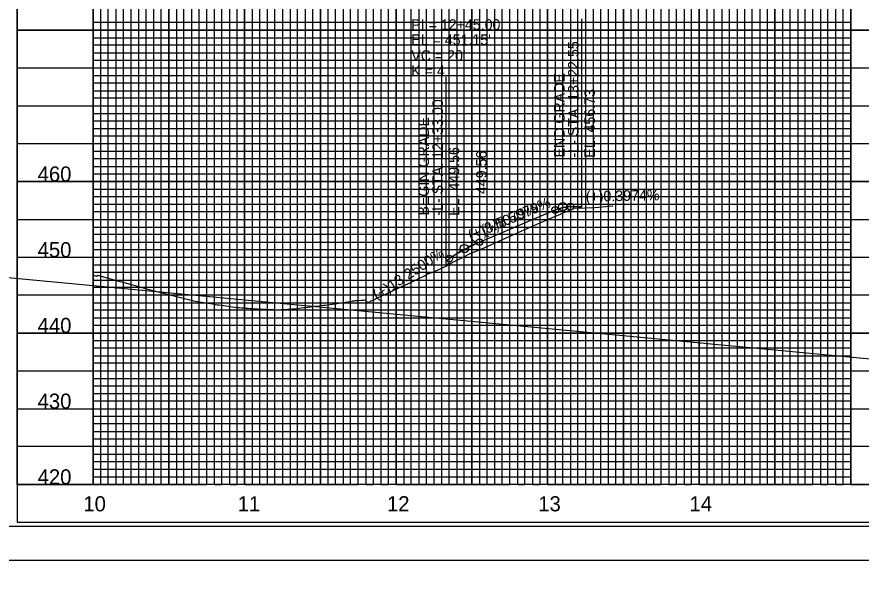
# Model space of a CAD drawing. Extents: x 571503 to 593215, y -77195 to -51828.
# Drawn here: x 585926 to 586483, y -53731 to -53362 of the extents above; entities that cross this region are included whole.
import ezdxf

# ---------------------------------------------------------------- set-up
doc = ezdxf.new("R2010")
doc.units = 0
for name, color, linetype in [('Default', 7, 'Continuous'), ('Exist Vertical Profile Ground Line', 7, 'Continuous'), ('Exist Vertical Profile Horizontal Axis Label Major', 7, 'Continuous'), ('Exist Vertical Profile Vertical Axis Label', 7, 'Continuous'), ('Prop PFL Text', 7, 'Continuous'), ('Prop Vertical Profile Curve Label', 7, 'Continuous'), ('Prop Vertical Profile Grade', 7, 'Continuous'), ('Prop Vertical Profile Grade Label', 7, 'Continuous'), ('Prop VPI Label', 7, 'Continuous'), ('Sheet Clip Boundary CELL', 7, 'Continuous'), ('Sheet DOT Grid CELL', 7, 'Continuous'), ('Sheet Plot Border Inside CELL', 7, 'Continuous'), ('Sheet Plot Border Outside CELL', 7, 'Continuous'), ('Sheet Profile CELL', 7, 'Continuous'), ('Sheet Profile Grid Major CELL', 7, 'Continuous'), ('Sheet Profile Grid Middle CELL', 7, 'Continuous'), ('Sheet Profile Grid Minor CELL', 7, 'Continuous')]:
    doc.layers.add(name, color=color, linetype=linetype)

msp = doc.modelspace()

# ---------------------------------------------------------------- linework, layer by layer
at = {"layer": 'Default'}
msp.add_line((585925.93, -53671.12), (585975.93, -53671.12), dxfattribs=at)
at = {"layer": 'Exist Vertical Profile Ground Line'}
for points in [[(586199.68, -53531.22), (586206.18, -53528.39), (586209.14, -53526.7), (586212.57, -53524.71), (586220.67, -53520.84), (586224.86, -53518.65), (586226.58, -53517.88), (586234.51, -53514.55), (586252.46, -53506.44), (586266.41, -53500.35), (586279.93, -53494.38), (586283.99, -53492.92), (586286.24, -53491.75), (586287.94, -53490.99), (586289.4, -53490.48), (586290.66, -53490), (586291.54, -53489.74)], [(586291.54, -53489.74), (586293.26, -53488.87), (586293.34, -53488.82), (586293.54, -53488.77), (586307.39, -53488.18), (586318.8, -53487.13), (586318.98, -53487.12)], [(585975.93, -53532.69), (585975.94, -53532.69), (585977.31, -53533.36), (585978.23, -53533.49), (585979.04, -53532.99), (585993.54, -53537.05), (585994.82, -53537.32), (586010.54, -53541.64), (586012.14, -53542.08), (586028.41, -53546.45), (586043.24, -53550.02), (586050.43, -53551.22), (586051.89, -53551.47), (586053.35, -53551.71), (586054.81, -53551.95), (586056.28, -53552.2), (586056.82, -53552.29), (586057.74, -53552.41), (586059.2, -53552.6), (586060.67, -53552.8), (586062.13, -53553), (586063.59, -53553.19), (586065.06, -53553.39), (586066.52, -53553.59), (586067.98, -53553.79), (586069.45, -53553.98), (586070.91, -53554.18), (586072.09, -53554.34), (586072.37, -53554.36), (586073.84, -53554.47), (586075.3, -53554.58), (586076.76, -53554.68), (586078.23, -53554.79), (586079.69, -53554.89), (586081.15, -53555), (586082.62, -53555.1), (586084.08, -53555.21), (586084.53, -53555.24), (586085.54, -53555.28), (586087.01, -53555.33), (586088.47, -53555.39), (586089.93, -53555.44), (586091.4, -53555.5), (586092.86, -53555.56), (586094.32, -53555.62), (586095.79, -53555.68), (586097.25, -53555.74), (586097.79, -53555.76), (586098.71, -53555.71), (586100.17, -53555.64), (586101.64, -53555.56), (586103.1, -53555.49), (586104.56, -53555.41), (586106.03, -53555.34), (586107.24, -53555.28), (586107.49, -53555.25), (586108.95, -53555.07), (586110.42, -53554.9), (586111.88, -53554.72), (586113.34, -53554.54), (586114.81, -53554.36), (586116.27, -53554.18), (586117.73, -53554), (586119.2, -53553.82), (586120.24, -53553.69), (586120.66, -53553.64), (586122.12, -53553.48), (586123.59, -53553.31), (586125.05, -53553.14), (586126.51, -53552.97), (586127.98, -53552.8), (586129.44, -53552.63), (586130.9, -53552.46), (586130.99, -53552.45), (586132.37, -53552.23), (586133.83, -53552.01), (586135.29, -53551.79), (586136.76, -53551.56), (586138.22, -53551.34), (586139.68, -53551.12), (586141.15, -53550.89), (586142.61, -53550.67), (586144.07, -53550.45), (586145.53, -53550.23), (586147, -53550.01), (586147.41, -53549.95), (586148.46, -53549.79), (586149.1, -53549.7), (586149.92, -53549.64), (586151.39, -53549.55), (586152.85, -53549.45), (586154.31, -53549.36), (586155.07, -53549.31), (586155.78, -53549.52), (586156.15, -53549.63), (586156.19, -53549.64), (586156.59, -53550.55), (586156.79, -53551.2), (586156.86, -53551.37), (586157.24, -53551.12), (586157.8, -53550.73)], [(586157.8, -53550.73), (586158.7, -53550.31), (586159.1, -53550.13), (586159.44, -53549.94), (586160.17, -53549.59), (586161.63, -53548.9), (586163.09, -53548.21), (586164.56, -53547.52), (586166.02, -53546.83), (586167.48, -53546.14), (586167.78, -53546), (586168.95, -53545.45), (586170.41, -53544.76), (586171.87, -53544.07), (586173.34, -53543.39), (586174.8, -53542.7), (586176.26, -53542.01), (586177.73, -53541.32), (586179.19, -53540.63), (586180.65, -53539.95), (586182.12, -53539.26), (586183.58, -53538.58), (586185.04, -53537.89), (586194.75, -53533.34), (586197.13, -53531.9), (586197.77, -53531.72), (586198.96, -53531.26), (586199.68, -53531.22)]]:
    msp.add_lwpolyline(points, dxfattribs=at)
at = {"layer": 'Prop PFL Text'}
msp.add_line((571620.66, -52186.29), (592499.52, -54154.87), dxfattribs=at)
at = {"layer": 'Prop Vertical Profile Curve Label'}
for centre in [(586280.93, -53489.85), (586290.93, -53487.62), (586230.93, -53511.12), (586210.93, -53522)]:
    msp.add_circle(centre, 2.25, dxfattribs=at)
at = {"layer": 'Prop Vertical Profile Grade'}
for p, q in [((586230.93, -53511.12), (586280.93, -53489.85)), ((586290.93, -53487.62), (586298.48, -53487.47)), ((586296.21, -53487.77), (586298.48, -53487.73)), ((586208.93, -53523.32), (586210.93, -53522)), ((586208.93, -53526.07), (586210.93, -53524.96))]:
    msp.add_line(p, q, dxfattribs=at)
for points in [[(586280.93, -53489.85), (586281.13, -53489.77), (586281.33, -53489.68), (586281.53, -53489.6), (586281.73, -53489.52), (586281.93, -53489.44), (586282.13, -53489.37), (586282.33, -53489.29), (586282.53, -53489.22), (586282.73, -53489.15), (586282.93, -53489.08), (586283.13, -53489.01), (586283.33, -53488.95), (586283.53, -53488.88), (586283.73, -53488.82), (586283.93, -53488.76), (586284.13, -53488.7), (586284.33, -53488.64), (586284.53, -53488.58), (586284.73, -53488.53), (586284.93, -53488.47), (586285.13, -53488.42), (586285.33, -53488.37), (586285.53, -53488.32), (586285.73, -53488.27), (586285.93, -53488.23), (586286.13, -53488.19), (586286.33, -53488.14), (586286.53, -53488.1), (586286.73, -53488.06), (586286.93, -53488.03), (586287.13, -53487.99), (586287.33, -53487.96), (586287.53, -53487.93), (586287.73, -53487.89), (586287.93, -53487.87), (586288.13, -53487.84), (586288.33, -53487.81), (586288.53, -53487.79), (586288.73, -53487.77), (586288.93, -53487.74), (586289.13, -53487.72), (586289.33, -53487.71), (586289.53, -53487.69), (586289.73, -53487.68), (586289.93, -53487.66), (586290.13, -53487.65), (586290.33, -53487.64), (586290.53, -53487.63), (586290.73, -53487.63), (586290.93, -53487.62)], [(586210.93, -53522), (586211.33, -53521.73), (586211.73, -53521.47), (586212.13, -53521.21), (586212.53, -53520.95), (586212.93, -53520.7), (586213.33, -53520.44), (586213.73, -53520.19), (586214.13, -53519.94), (586214.53, -53519.69), (586214.93, -53519.44), (586215.33, -53519.2), (586215.73, -53518.95), (586216.13, -53518.71), (586216.53, -53518.47), (586216.93, -53518.24), (586217.33, -53518), (586217.73, -53517.77), (586218.13, -53517.54), (586218.53, -53517.31), (586218.93, -53517.08), (586219.33, -53516.85), (586219.73, -53516.63), (586220.13, -53516.41), (586220.53, -53516.18), (586220.93, -53515.97), (586221.33, -53515.75), (586221.73, -53515.53), (586222.13, -53515.32), (586222.53, -53515.11), (586222.93, -53514.9), (586223.33, -53514.69), (586223.73, -53514.49), (586224.13, -53514.29), (586224.53, -53514.08), (586224.93, -53513.89), (586225.33, -53513.69), (586225.73, -53513.49), (586226.13, -53513.3), (586226.53, -53513.11), (586226.93, -53512.92), (586227.33, -53512.73), (586227.73, -53512.54), (586228.13, -53512.36), (586228.53, -53512.17), (586228.93, -53511.99), (586229.33, -53511.82), (586229.73, -53511.64), (586230.13, -53511.46), (586230.53, -53511.29), (586230.93, -53511.12)]]:
    msp.add_spline(points, degree=3, dxfattribs=at)
at = {"layer": 'Prop VPI Label'}
for p, q in [((586298.48, -53487.73), (586298.48, -53363.6)), ((586208.93, -53526.07), (586208.93, -53401.94)), ((586280.93, -53489.85), (586283.4, -53488.8)), ((586290.93, -53487.62), (586288.68, -53487.67)), ((586230.93, -53511.12), (586223.46, -53514.3)), ((586210.93, -53522), (586218.64, -53516.89))]:
    msp.add_line(p, q, dxfattribs=at)
for centre in [(586285.93, -53487.72), (586220.93, -53515.37)]:
    msp.add_circle(centre, 2.75, dxfattribs=at)
at = {"layer": 'Sheet Clip Boundary CELL'}
msp.add_lwpolyline([(585975.93, -53171.12), (587375.93, -53171.12), (587375.93, -53671.12), (585975.93, -53671.12)], close=True, dxfattribs=at)
at = {"layer": 'Sheet DOT Grid CELL'}
for p, q in [((585925.93, -53671.12), (585925.93, -53171.12)), ((585975.93, -53671.12), (585975.93, -53171.12)), ((585975.93, -53171.12), (585975.93, -53671.12)), ((586025.93, -53671.12), (586025.93, -53171.12)), ((586025.93, -53171.12), (586025.93, -53671.12)), ((586075.93, -53671.12), (586075.93, -53171.12)), ((586075.93, -53171.12), (586075.93, -53671.12)), ((586125.93, -53671.12), (586125.93, -53171.12)), ((586125.93, -53171.12), (586125.93, -53671.12)), ((586175.93, -53671.12), (586175.93, -53171.12)), ((586175.93, -53171.12), (586175.93, -53671.12)), ((586225.93, -53671.12), (586225.93, -53171.12)), ((586225.93, -53171.12), (586225.93, -53671.12)), ((586275.93, -53671.12), (586275.93, -53171.12)), ((586275.93, -53171.12), (586275.93, -53671.12)), ((586325.93, -53671.12), (586325.93, -53171.12)), ((586325.93, -53171.12), (586325.93, -53671.12)), ((586375.93, -53671.12), (586375.93, -53171.12)), ((586375.93, -53171.12), (586375.93, -53671.12)), ((586425.93, -53671.12), (586425.93, -53171.12)), ((586425.93, -53171.12), (586425.93, -53671.12)), ((586475.93, -53671.12), (586475.93, -53171.12)), ((586475.93, -53171.12), (586475.93, -53671.12)), ((585925.93, -53371.12), (587425.93, -53371.12)), ((585925.93, -53371.12), (587425.82, -53371.12)), ((585925.93, -53421.12), (587425.93, -53421.12)), ((585925.93, -53421.12), (587425.82, -53421.12)), ((585925.93, -53471.12), (587425.93, -53471.12)), ((585925.93, -53471.12), (587425.82, -53471.12)), ((585925.93, -53521.12), (587425.82, -53521.12)), ((585925.93, -53521.12), (586525.93, -53521.12)), ((585925.93, -53571.12), (587425.82, -53571.12)), ((585925.93, -53621.12), (587425.93, -53621.12)), ((585925.93, -53621.12), (587425.82, -53621.12))]:
    msp.add_line(p, q, dxfattribs=at)
at = {"layer": 'Sheet Plot Border Inside CELL'}
msp.add_lwpolyline([(585771.93, -53698.67), (587438.43, -53698.67), (587438.43, -52643.57), (585771.93, -52643.57)], close=True, dxfattribs=at)
at = {"layer": 'Sheet Plot Border Outside CELL'}
msp.add_lwpolyline([(585758.93, -53721.12), (587442.93, -53721.12), (587442.93, -52621.12), (585758.93, -52621.12)], close=True, dxfattribs=at)
at = {"layer": 'Sheet Profile CELL'}
for p, q in [((587425.93, -53671.12), (585925.93, -53671.12)), ((585925.93, -53696.12), (587425.93, -53696.12)), ((585925.93, -53696.12), (585925.93, -53696.12)), ((585925.93, -53696.12), (585925.93, -53696.12)), ((585925.93, -53696.12), (585925.93, -53696.12)), ((585925.93, -53696.12), (585925.93, -53696.12)), ((585925.93, -53696.12), (585925.93, -53696.12)), ((585925.93, -53696.12), (585925.93, -53696.12)), ((585925.93, -53696.12), (585925.93, -53696.12)), ((585758.93, -53721.12), (587442.93, -53721.12))]:
    msp.add_line(p, q, dxfattribs=at)
msp.add_lwpolyline([(587425.93, -52646.12), (585925.93, -52646.12), (585925.93, -53696.12), (587425.93, -53696.12)], close=True, dxfattribs=at)
msp.add_lwpolyline([(585963.43, -53696.12), (585963.43, -53696.12)], dxfattribs=at)
at = {"layer": 'Sheet Profile Grid Major CELL'}
for p, q in [((585925.93, -53671.12), (585925.93, -53671.12)), ((586475.93, -53671.12), (586475.93, -53671.12))]:
    msp.add_line(p, q, dxfattribs=at)
for points in [[(585975.93, -53171.12), (585975.93, -53671.12), (586025.93, -53671.12), (586025.93, -53171.12), (586075.93, -53171.12), (586075.93, -53671.12), (586125.93, -53671.12), (586125.93, -53171.12), (586175.93, -53171.12), (586175.93, -53671.12), (586225.93, -53671.12), (586225.93, -53171.12), (586275.93, -53171.12), (586275.93, -53671.12), (586325.93, -53671.12), (586325.93, -53171.12), (586375.93, -53171.12), (586375.93, -53671.12), (586425.93, -53671.12), (586425.93, -53171.12), (586475.93, -53171.12), (586475.93, -53671.12), (586525.93, -53671.12)], [(587425.93, -53371.12), (585925.93, -53371.12), (585925.93, -53421.12), (587425.93, -53421.12)], [(587425.93, -53471.12), (585925.93, -53471.12), (585925.93, -53521.12), (587425.93, -53521.12)], [(587425.93, -53571.12), (585925.93, -53571.12), (585925.93, -53571.12), (585925.93, -53621.12), (587425.93, -53621.12)], [(587425.93, -53671.12), (585925.93, -53671.12)]]:
    msp.add_lwpolyline(points, dxfattribs=at)
at = {"layer": 'Sheet Profile Grid Middle CELL'}
for p, q in [((586000.93, -53171.12), (586000.93, -53671.12)), ((586050.93, -53671.12), (586050.93, -53171.12)), ((586100.93, -53171.12), (586100.93, -53671.12)), ((586150.93, -53671.12), (586150.93, -53171.12)), ((586200.93, -53171.12), (586200.93, -53671.12)), ((586250.93, -53671.12), (586250.93, -53171.12)), ((586300.93, -53171.12), (586300.93, -53671.12)), ((586350.93, -53671.12), (586350.93, -53171.12)), ((586400.93, -53171.12), (586400.93, -53671.12)), ((586450.93, -53671.12), (586450.93, -53171.12)), ((586000.93, -53671.12), (586050.93, -53671.12)), ((586100.93, -53671.12), (586150.93, -53671.12)), ((586200.93, -53671.12), (586250.93, -53671.12)), ((586300.93, -53671.12), (586350.93, -53671.12)), ((586400.93, -53671.12), (586450.93, -53671.12))]:
    msp.add_line(p, q, dxfattribs=at)
for points in [[(587425.93, -53346.12), (585925.93, -53346.12), (585925.93, -53396.12), (587425.93, -53396.12)], [(587425.93, -53446.12), (585925.93, -53446.12), (585925.93, -53496.12), (587425.93, -53496.12)], [(587425.93, -53546.12), (585925.93, -53546.12), (585925.93, -53596.12), (587425.93, -53596.12)], [(587425.93, -53646.12), (585925.93, -53646.12)]]:
    msp.add_lwpolyline(points, dxfattribs=at)
at = {"layer": 'Sheet Profile Grid Minor CELL'}
for p, q in [((586475.93, -53366.03), (585975.93, -53365.97)), ((585975.93, -53376.12), (586475.93, -53376.12)), ((586475.93, -53381.12), (585975.93, -53381.12)), ((585975.93, -53386.12), (586475.93, -53386.12)), ((586475.93, -53391.12), (585975.93, -53391.12)), ((585975.93, -53401.12), (586475.93, -53401.12)), ((586475.93, -53406.12), (585975.93, -53406.12)), ((585975.93, -53411.12), (586475.93, -53411.12)), ((586475.93, -53416.12), (585975.93, -53416.12)), ((585975.93, -53426.12), (586475.93, -53426.12)), ((586475.93, -53431.12), (585975.93, -53431.12)), ((585975.93, -53436.12), (586475.93, -53436.12)), ((586475.93, -53441.12), (585975.93, -53441.12)), ((585975.93, -53451.12), (586475.93, -53451.12)), ((586475.93, -53456.12), (585975.93, -53456.12)), ((585975.93, -53461.12), (586475.93, -53461.12)), ((586475.93, -53466.12), (585975.93, -53466.12)), ((585975.93, -53476.12), (586475.93, -53476.12)), ((586475.93, -53481.12), (585975.93, -53481.12)), ((585975.93, -53486.12), (586475.93, -53486.12)), ((586475.93, -53491.12), (585975.93, -53491.12)), ((585975.93, -53501.12), (586475.93, -53501.12)), ((586475.93, -53506.12), (585975.93, -53506.12)), ((585975.93, -53511.12), (586475.93, -53511.12)), ((586475.93, -53516.12), (585975.93, -53516.12)), ((585975.93, -53526.12), (586475.93, -53526.12)), ((586475.93, -53531.12), (585975.93, -53531.12)), ((585975.93, -53536.12), (586475.93, -53536.12)), ((586475.93, -53541.12), (585975.93, -53541.12)), ((585975.93, -53551.12), (586475.93, -53551.12)), ((586475.93, -53556.12), (585975.93, -53556.12)), ((585975.93, -53561.12), (586475.93, -53561.12)), ((586475.93, -53566.12), (585975.93, -53566.12)), ((585975.93, -53576.12), (586475.93, -53576.12)), ((586475.93, -53581.12), (585975.93, -53581.12)), ((585975.93, -53586.12), (586475.93, -53586.12)), ((586475.93, -53591.12), (585975.93, -53591.12)), ((585975.93, -53601.12), (586475.93, -53601.12)), ((586475.93, -53606.12), (585975.93, -53606.12)), ((585975.93, -53611.12), (586475.93, -53611.12)), ((586475.93, -53616.12), (585975.93, -53616.12)), ((585975.93, -53626.12), (586475.93, -53626.12)), ((586475.93, -53631.12), (585975.93, -53631.12)), ((585975.93, -53636.12), (586475.93, -53636.12)), ((586475.93, -53641.12), (585975.93, -53641.12)), ((585975.93, -53651.12), (586475.93, -53651.12)), ((586475.93, -53656.12), (585975.93, -53656.12)), ((585975.93, -53661.12), (586475.93, -53661.12)), ((585975.93, -53666.12), (586475.93, -53666.12))]:
    msp.add_line(p, q, dxfattribs=at)
for points in [[(585980.93, -53171.12), (585980.93, -53671.12), (585985.93, -53671.12), (585985.93, -53171.12)], [(585990.93, -53171.12), (585990.93, -53671.12), (585995.93, -53671.12), (585995.93, -53171.12)], [(586005.93, -53171.12), (586005.93, -53671.12), (586010.93, -53671.12), (586010.93, -53171.12)], [(586015.93, -53171.12), (586015.93, -53671.12), (586020.93, -53671.12), (586030.93, -53671.12), (586035.93, -53671.12), (586035.93, -53171.12)], [(586020.93, -53671.12), (586020.93, -53171.12), (586030.93, -53171.12), (586030.93, -53671.12)], [(586040.93, -53171.12), (586040.93, -53671.12), (586045.93, -53671.12), (586045.93, -53171.12)], [(586055.93, -53171.12), (586055.93, -53671.12), (586060.93, -53671.12), (586060.93, -53171.12)], [(586065.93, -53171.12), (586065.93, -53671.12), (586070.93, -53671.12), (586070.93, -53171.12)], [(586080.93, -53171.12), (586080.93, -53671.12), (586085.93, -53671.12), (586085.93, -53171.12)], [(586090.93, -53171.12), (586090.93, -53671.12), (586095.93, -53671.12), (586095.93, -53171.12)], [(586105.93, -53171.12), (586105.93, -53671.12), (586110.93, -53671.12), (586110.93, -53171.12)], [(586115.93, -53171.12), (586115.93, -53671.12), (586120.93, -53671.12), (586120.93, -53171.12)], [(586130.93, -53171.12), (586130.93, -53671.12), (586135.93, -53671.12), (586135.93, -53171.12)], [(586140.93, -53171.12), (586140.93, -53671.12), (586145.93, -53671.12), (586145.93, -53171.12)], [(586155.93, -53171.12), (586155.93, -53671.12), (586160.93, -53671.12), (586160.93, -53171.12)], [(586165.93, -53171.12), (586165.93, -53671.12), (586170.93, -53671.12), (586170.93, -53171.12)], [(586180.93, -53171.12), (586180.93, -53671.12), (586185.93, -53671.12), (586185.93, -53171.12)], [(586190.93, -53171.12), (586190.93, -53671.12)], [(586190.93, -53671.12), (586195.93, -53671.12), (586195.93, -53171.12)], [(586205.93, -53171.12), (586205.93, -53671.12), (586210.93, -53671.12), (586210.93, -53171.12)], [(586215.93, -53171.12), (586215.93, -53671.12), (586220.93, -53671.12), (586220.93, -53171.12)], [(586230.93, -53171.12), (586230.93, -53671.12), (586235.93, -53671.12), (586235.93, -53171.12)], [(586240.93, -53171.12), (586240.93, -53671.12), (586245.93, -53671.12), (586245.93, -53171.12)], [(586255.93, -53171.12), (586255.93, -53671.12), (586260.93, -53671.12), (586260.93, -53171.12)], [(586265.93, -53171.12), (586265.93, -53671.12), (586270.93, -53671.12), (586270.93, -53171.12)], [(586280.93, -53171.12), (586280.93, -53671.12), (586285.93, -53671.12), (586285.93, -53171.12)], [(586290.93, -53171.12), (586290.93, -53671.12), (586295.93, -53671.12), (586295.93, -53171.12)], [(586305.93, -53171.12), (586305.93, -53671.12), (586310.93, -53671.12), (586310.93, -53171.12)], [(586315.93, -53171.12), (586315.93, -53671.12), (586320.93, -53671.12), (586320.93, -53171.12)], [(586330.93, -53171.12), (586330.93, -53671.12), (586335.93, -53671.12), (586335.93, -53171.12)], [(586340.93, -53171.12), (586340.93, -53671.12), (586345.93, -53671.12), (586345.93, -53171.12)], [(586355.93, -53171.12), (586355.93, -53671.12), (586360.93, -53671.12), (586360.93, -53171.12)], [(586365.93, -53171.12), (586365.93, -53671.12), (586370.93, -53671.12), (586370.93, -53171.12)], [(586380.93, -53171.12), (586380.93, -53671.12), (586385.93, -53671.12), (586385.93, -53171.12)], [(586390.93, -53171.12), (586390.93, -53671.12), (586395.93, -53671.12), (586395.93, -53171.12)], [(586405.93, -53171.12), (586405.93, -53671.12), (586410.93, -53671.12), (586410.93, -53171.12)], [(586415.93, -53171.12), (586415.93, -53671.12), (586420.93, -53671.12), (586420.93, -53171.12)], [(586430.93, -53171.12), (586430.93, -53671.12), (586435.93, -53671.12), (586435.93, -53171.12)], [(586440.93, -53171.12), (586440.93, -53671.12), (586445.93, -53671.12), (586445.93, -53171.12)], [(586455.93, -53171.12), (586455.93, -53671.12), (586460.93, -53671.12), (586460.93, -53171.12)], [(586465.93, -53171.12), (586465.93, -53671.12), (586470.93, -53671.12), (586470.93, -53171.12)]]:
    msp.add_lwpolyline(points, dxfattribs=at)

# ---------------------------------------------------------------- texts
at = {"layer": 'Exist Vertical Profile Horizontal Axis Label Major'}
for s, p in [('10', (585969.52, -53688.87)), ('11', (586071.36, -53688.87)), ('12', (586169.9, -53688.87)), ('13', (586269.74, -53688.87)), ('14', (586369.58, -53688.87))]:
    msp.add_text(s, height=10, dxfattribs=at).set_placement(p)
at = {"layer": 'Exist Vertical Profile Vertical Axis Label'}
for s, p in [('460', (585939.36, -53471.12)), ('450', (585939.36, -53521.12)), ('440', (585939.36, -53571.12)), ('430', (585939.36, -53621.12)), ('420', (585939.36, -53671.12))]:
    msp.add_text(s, height=10, dxfattribs=at).set_placement(p)
at = {"layer": 'Prop Vertical Profile Grade Label'}
for s, rotation, p in [('(+)0.3974%', 1.1382, (586301.13, -53484.42)), ('(+)8.5079%', 23.0446, (586233.85, -53506.62)), ('(+)8.5079%', 23.0446, (586225.23, -53510.28)), ('(+)13.2500%', 33.5245, (586163.46, -53549.85))]:
    msp.add_text(s, height=7, rotation=rotation, dxfattribs=at).set_placement(p)
at = {"layer": 'Prop VPI Label'}
for s, p in [('PI = 12+45.00', (586185.93, -53370.94)), ("EL = 451.15'", (586185.93, -53380.94)), ("VC = 20'", (586185.93, -53391.4)), ('K = 4', (586185.93, -53401.4))]:
    msp.add_text(s, height=7, dxfattribs=at).set_placement(p)
for s, p in [('-L- STA. 13+22.55', (586296.42, -53455.21)), ('END GRADE', (586287.12, -53455.21)), ('EL. 456.73', (586307.15, -53455.34)), ('-L- STA. 12+33.00', (586206.87, -53493.55)), ('BEGIN GRADE', (586197.57, -53493.55)), ('EL. 449.56', (586217.6, -53493.68)), ('449.56', (586235.71, -53479.39))]:
    msp.add_text(s, height=7, rotation=90, dxfattribs=at).set_placement(p)

doc.saveas('drawing.dxf')
